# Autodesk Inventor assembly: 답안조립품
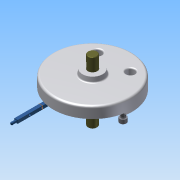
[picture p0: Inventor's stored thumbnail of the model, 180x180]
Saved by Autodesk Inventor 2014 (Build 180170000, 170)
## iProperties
Created: 2015-06
Part Number: 답안조립품
Document SubType Name: Assembly
Designer: Administrator
Author: Administrator
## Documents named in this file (8)
- C:\Documents and Settings\Administrator\바탕 화면\450631V1018\답안조립품.iam
- C:\Documents and Settings\Administrator\바탕 화면\450631V1018\1-본체.ipt
- C:\Documents and Settings\Administrator\바탕 화면\450631V1018\덮개.ipt
- C:\Documents and Settings\Administrator\바탕 화면\450631V1018\베어링62_22.ipt
- C:\Documents and Settings\Administrator\바탕 화면\450631V1018\축.ipt
- C:\Documents and Settings\Administrator\바탕 화면\450631V1018\멈춤링.ipt
- C:\Documents and Settings\Administrator\바탕 화면\450631V1018\슬라이더2.ipt
- C:\Documents and Settings\Administrator\바탕 화면\450631V1018\M10x35.ipt
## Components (7 placed, 4 different names)
1. 1-본체:1
2. KS B 2023 62/22 - 22 x 50 x 14:1
3. KS B 2023 62/22 - 22 x 50 x 14:2
4. KS B 1336 22 x 1.2:1
5. KS B 1336 22 x 1.2:2
6. KS B 1003 - 미터 M 10 x 35:1
7. KS B 1003 - 미터 M 10 x 35:2
